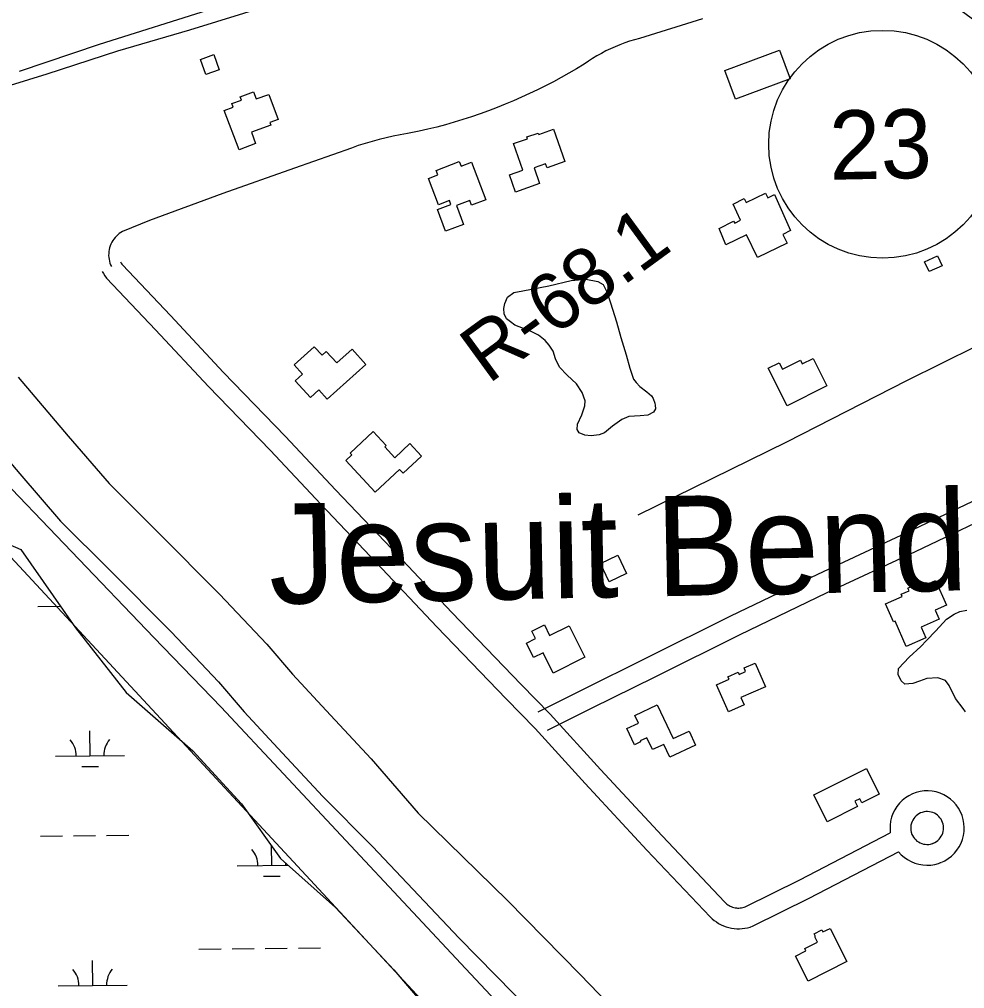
# Model space of a CAD drawing. Extents: x 3684037 to 3722149, y 433263 to 459021.
# Drawn here: x 3694344 to 3695714, y 454824 to 456228 of the extents above; entities that cross this region are included whole.
import ezdxf

# ---------------------------------------------------------------- set-up
doc = ezdxf.new("R2010")
doc.units = 0
for name, color, linetype in [('V-BLDG-OTLN', 7, 'Continuous'), ('V-LEVE-TOET', 7, 'Continuous'), ('V-RIVR-RANG-IDEN', 7, 'Continuous'), ('V-ROAD-CNTR', 7, 'Continuous'), ('V-ROAD-IDEN', 7, 'Continuous'), ('V-SITE-VEGE', 7, 'Continuous'), ('V-TOPO-GNAM-IDEN', 7, 'Continuous'), ('V-TOPO-SHOR', 7, 'Continuous'), ('V-WETL-SWMP', 7, 'Continuous')]:
    doc.layers.add(name, color=color, linetype=linetype)

msp = doc.modelspace()

# ---------------------------------------------------------------- linework, layer by layer
at = {"layer": 'V-BLDG-OTLN'}
for points in [[(3695366.6, 456153.9), (3695445.8, 456183.5), (3695461.3, 456141.9), (3695382.1, 456112.3)], [(3694626.2, 456176.8), (3694634, 456154.8), (3694614.7, 456147.9), (3694606.9, 456169.9)], [(3694705.9, 456119.2), (3694719.4, 456083.1), (3694707.3, 456078.5), (3694708.7, 456074.8), (3694680.7, 456064.3), (3694686.8, 456048.1), (3694662.8, 456039.1), (3694641.4, 456096), (3694654.2, 456100.8), (3694652.3, 456105.9), (3694666.3, 456111.1), (3694664.6, 456115.7), (3694683.8, 456122.9), (3694687.6, 456112.8)], [(3695118.6, 456068.9), (3695135.1, 456021.8), (3695109.1, 456012.7), (3695107.1, 456018.5), (3695090.5, 456012.7), (3695098.4, 455990), (3695063.4, 455977.7), (3695054.7, 456002.8), (3695073.8, 456009.5), (3695060.4, 456047.9), (3695080.9, 456055), (3695080, 456057.6), (3695096.3, 456063.3), (3695097, 456061.3)], [(3694988.1, 455930.9), (3694962.2, 455921.1), (3694950.3, 455952.3), (3694969.9, 455959.8), (3694967.8, 455965.4), (3694951.9, 455959.3), (3694937.4, 455997.5), (3694951, 456002.7), (3694948.6, 456009.1), (3694982, 456021.8), (3694984.5, 456015.1), (3694999.6, 456020.9), (3695020.3, 455966.4), (3694999.7, 455958.6), (3694997.1, 455965.5), (3694977.7, 455958.2)], [(3695457, 455903.6), (3695414.3, 455882.8), (3695398.3, 455915.6), (3695368.4, 455901.3), (3695358.4, 455925.1), (3695379.2, 455935.8), (3695381.1, 455932.7), (3695389.7, 455937), (3695378.8, 455960.4), (3695394.8, 455968.4), (3695397.6, 455962.6), (3695425.9, 455976.3), (3695429.3, 455969.4), (3695438.9, 455974), (3695462.2, 455921.9), (3695450.7, 455916.4)], [(3695681.6, 455871.1), (3695662.8, 455862.5), (3695656.3, 455876.9), (3695675.1, 455885.5)], [(3694846.4, 455728.1), (3694790.4, 455677.6), (3694778.2, 455691.1), (3694766.1, 455680.1), (3694744.1, 455704.5), (3694754.5, 455714), (3694742.5, 455727.4), (3694771.8, 455753.8), (3694783, 455741.3), (3694789.2, 455746.9), (3694804.3, 455730.2), (3694826.5, 455750.2)], [(3695514.8, 455697.2), (3695457.3, 455668), (3695429.7, 455722.5), (3695445.7, 455730.6), (3695450.6, 455721.1), (3695476.3, 455734.2), (3695479, 455728.8), (3695494.8, 455736.8)], [(3694823.8, 455599.6), (3694857.3, 455630.8), (3694876.2, 455610.6), (3694874, 455608.6), (3694888.6, 455593), (3694910.4, 455613.4), (3694927.2, 455595.3), (3694900.5, 455570.4), (3694895.1, 455576.1), (3694859.9, 455543.2), (3694817.4, 455588.8), (3694826.2, 455597)], [(3695199.3, 455413.3), (3695186.7, 455439.9), (3695211.9, 455451.8), (3695224.5, 455425.2)], [(3695629.8, 455319.3), (3695613.5, 455356.1), (3695611.4, 455355.2), (3695599.8, 455381.4), (3695623.7, 455392), (3695622.3, 455395.2), (3695633.9, 455400.3), (3695632.2, 455404.1), (3695644.4, 455409.6), (3695645.6, 455407), (3695657.6, 455412.3), (3695658.9, 455409.3), (3695672.1, 455415.1), (3695687.9, 455379.5), (3695671.5, 455372.2), (3695677.4, 455358.9), (3695651.4, 455347.4), (3695658.3, 455331.9)], [(3695141.1, 455349.7), (3695163.8, 455303.9), (3695117.9, 455281.1), (3695103.4, 455310.2), (3695089.7, 455303.4), (3695079.2, 455324.5), (3695092.5, 455331.1), (3695087.2, 455341.9), (3695105.3, 455351), (3695112.9, 455335.7)], [(3695410.6, 455295.6), (3695425.6, 455261.2), (3695390.2, 455245.7), (3695394.9, 455234.9), (3695372.1, 455224.9), (3695354.9, 455264.1), (3695372.9, 455272), (3695371.2, 455275.8), (3695386.1, 455282.4), (3695387.5, 455279.2), (3695396.9, 455283.3), (3695394.6, 455288.7)], [(3695287.2, 455159), (3695278.2, 455177.8), (3695261.9, 455170.1), (3695253.7, 455187.4), (3695244.1, 455182.9), (3695244.8, 455181.4), (3695236, 455177.2), (3695224.8, 455200.7), (3695241.5, 455208.7), (3695236.4, 455219.5), (3695268.9, 455235), (3695292.1, 455186.2), (3695314.9, 455197.1), (3695324.5, 455176.8)], [(3695495.7, 455104.5), (3695572, 455142.7), (3695590.5, 455105.6), (3695565.5, 455093.1), (3695562.6, 455098.9), (3695555.4, 455095.3), (3695559.2, 455087.6), (3695515.1, 455065.6)], [(3695519.4, 454911.3), (3695543.7, 454863.1), (3695487.8, 454834.8), (3695469.4, 454871.2), (3695484.4, 454878.8), (3695482.9, 454881.9), (3695501.1, 454891.1), (3695497.1, 454899), (3695498.4, 454899.7), (3695496.5, 454903.5), (3695507.5, 454909), (3695509, 454906)]]:
    msp.add_lwpolyline(points, close=True, dxfattribs=at)
at = {"layer": 'V-LEVE-TOET'}
for points in [[(3696627.9, 453001), (3696461.1, 453218.4), (3696075.3, 453606.9), (3695412.9, 454284.5), (3694747.3, 455001.3), (3694132.9, 455662.7), (3693840.2, 455975.5), (3693606.8, 456218.9), (3693390.2, 456442.3), (3693137.7, 456709), (3692943.4, 456915.7)], [(3693028.7, 456916.7), (3693038.7, 456906.9), (3693324.6, 456624.6), (3693426.3, 456503.8), (3693538.5, 456377.8), (3693732.6, 456194.4), (3693929.1, 455975.9), (3694180.6, 455706.2), (3694539.2, 455332.5), (3694636.7, 455231.9), (3694998.1, 454845.3), (3695305.2, 454518.5), (3695635.9, 454168.1), (3695971, 453817), (3696154, 453621.9), (3696470.1, 453290.7), (3696591.5, 453172.8), (3696683.7, 453049.7), (3696799.1, 452898.8)]]:
    msp.add_lwpolyline(points, dxfattribs=at)
at = {"layer": 'V-ROAD-CNTR'}
for points in [[(3695334.2, 456228.7), (3695242.9, 456200.2), (3695235.7, 456198.3), (3695228.7, 456196.1), (3695221.7, 456193.7), (3695214.7, 456191.1), (3695207.9, 456188.3), (3695201.2, 456185.3), (3695194.5, 456182.1), (3695188, 456178.7), (3695181.5, 456175), (3695175.2, 456171.2), (3695169, 456167.2), (3695162.9, 456162.9), (3695152, 456156.3), (3695140.9, 456149.8), (3695129.7, 456143.6), (3695118.4, 456137.5), (3695107, 456131.6), (3695095.5, 456125.9), (3695083.9, 456120.3), (3695072.2, 456115), (3695060.4, 456109.9), (3695048.6, 456104.9), (3695036.7, 456100.2), (3695024.4, 456095.5), (3695012, 456091), (3694999.6, 456086.7), (3694987.1, 456082.7), (3694974.5, 456078.9), (3694961.9, 456075.3), (3694949.2, 456072), (3694936.4, 456068.9), (3694923.6, 456066), (3694906.9, 456062.8), (3694896.5, 456060.9), (3694886.3, 456058.8), (3694876, 456056.5), (3694865.8, 456054), (3694855.7, 456051.2), (3694845.6, 456048.2), (3694835.6, 456045), (3694825.7, 456041.5), (3694743.3, 456012.5), (3694639.1, 455975.5), (3694533.2, 455936.7), (3694493.8, 455920.8), (3694491.4, 455919.3), (3694489.1, 455917.7), (3694486.9, 455915.9), (3694484.9, 455914), (3694483, 455911.9), (3694481.2, 455909.7), (3694479.6, 455907.4), (3694478.2, 455905), (3694477, 455902.4), (3694476, 455899.8), (3694475.1, 455897.1), (3694474.5, 455894.4), (3694474, 455891.6), (3694473.8, 455888.8), (3694473.7, 455886), (3694473.9, 455883.2), (3694474.3, 455880.4), (3694474.8, 455877.7), (3694475.6, 455875), (3694476.6, 455872.3), (3694477.7, 455869.8)], [(3696132.2, 455994.5), (3696130.6, 455989.7), (3696128.8, 455985), (3696126.9, 455980.4), (3696124.7, 455975.9), (3696122.3, 455971.5), (3696119.7, 455967.2), (3696116.9, 455963), (3696114, 455958.9), (3696110.8, 455955), (3696107.5, 455951.2), (3696104.1, 455947.6), (3696100.4, 455944.1), (3696096.7, 455940.8), (3696092.7, 455937.7), (3696010.6, 455892.6), (3695833, 455804.9), (3695630, 455704.1), (3695456, 455615.6), (3695240.7, 455510)], [(3694490.9, 455876.8), (3694492, 455874.8), (3694492.9, 455873.4), (3694493.7, 455872.3), (3694563.4, 455798.8), (3694640.3, 455716.6), (3694729.7, 455624.4), (3694803.1, 455546.1), (3694883.6, 455461.5), (3694971.3, 455368.7), (3695071.5, 455264.4), (3695113.5, 455221.4), (3695186.4, 455141.3), (3695275.8, 455045.1), (3695366.8, 454949.1), (3695368.3, 454947.7), (3695369.8, 454946.5), (3695371.3, 454945.3), (3695372.9, 454944.3), (3695374.5, 454943.5), (3695376.2, 454942.7), (3695378, 454942), (3695379.8, 454941.5), (3695381.7, 454941.1), (3695383.5, 454940.8), (3695385.4, 454940.7), (3695387.3, 454940.7), (3695389.2, 454940.8), (3695391, 454941), (3695392.9, 454941.4), (3695394.7, 454941.9), (3695396.1, 454942.4), (3695475.6, 454981.5), (3695606.6, 455049.7)], [(3694464.5, 455862.7), (3694466.1, 455859.7), (3694468.1, 455856.4), (3694470.7, 455853), (3694541.6, 455778.2), (3694618.5, 455695.9), (3694708, 455603.7), (3694781.3, 455525.5), (3694861.8, 455440.9), (3694949.5, 455348), (3695049.9, 455243.5), (3695091.7, 455200.8), (3695164.3, 455121), (3695253.9, 455024.6), (3695345.5, 454928), (3695348.3, 454925.3), (3695351.3, 454922.8), (3695354.5, 454920.5), (3695357.8, 454918.4), (3695361.3, 454916.5), (3695364.9, 454914.9), (3695368.6, 454913.5), (3695372.4, 454912.4), (3695376.3, 454911.6), (3695380.2, 454911), (3695384.1, 454910.7), (3695388.1, 454910.7), (3695392, 454910.9), (3695395.9, 454911.4), (3695399.8, 454912.2), (3695403.6, 454913.2), (3695407.7, 454914.7), (3695489.1, 454954.8), (3695618.6, 455022.2)], [(3696079.8, 455661.5), (3696015.7, 455632.4), (3695912.6, 455584.1), (3695784.2, 455524.1), (3695642.8, 455456.8), (3695513.7, 455396.8), (3695388.4, 455336.4), (3695265.4, 455275.3), (3695174.1, 455230.1), (3695109.3, 455197.7)], [(3695771.4, 455551.3), (3695630, 455484), (3695500.9, 455423.9), (3695375.2, 455363.3), (3695252, 455302.2), (3695160.7, 455257), (3695095.9, 455224.6)], [(3695681.1, 455007.1), (3695685.7, 455009.3), (3695690.7, 455012.4), (3695695.3, 455016), (3695699.5, 455020), (3695703.2, 455024.6), (3695706.5, 455029.4), (3695709.1, 455034.7), (3695711.2, 455040.1), (3695712.7, 455045.8), (3695713.6, 455051.6), (3695713.8, 455057.5), (3695713.4, 455063.3), (3695712.3, 455069.1), (3695710.7, 455074.7), (3695708.4, 455080.1), (3695705.6, 455085.3), (3695702.2, 455090), (3695698.3, 455094.4), (3695693.9, 455098.4), (3695689.2, 455101.8), (3695684.1, 455104.7), (3695678.7, 455107.1), (3695673.1, 455108.8), (3695667.4, 455109.9), (3695661.5, 455110.4), (3695655.7, 455110.3), (3695649.8, 455109.5), (3695644.2, 455108.1), (3695638.6, 455106), (3695633.4, 455103.4), (3695628.5, 455100.2), (3695623.9, 455096.6), (3695619.8, 455092.4), (3695616.1, 455087.8), (3695613, 455082.9), (3695610.4, 455077.6), (3695608.4, 455072.1), (3695607, 455066.4), (3695606.3, 455060.6), (3695606.2, 455054.7), (3695606.6, 455049.6)], [(3695668.3, 455034.2), (3695671.3, 455035.7), (3695673.5, 455037), (3695675.6, 455038.6), (3695677.4, 455040.4), (3695679.1, 455042.4), (3695680.5, 455044.6), (3695681.7, 455046.9), (3695682.6, 455049.3), (3695683.3, 455051.8), (3695683.7, 455054.4), (3695683.8, 455057), (3695683.6, 455059.6), (3695683.1, 455062.1), (3695682.4, 455064.6), (3695681.4, 455067), (3695680.1, 455069.3), (3695678.6, 455071.4), (3695676.9, 455073.3), (3695675, 455075.1), (3695672.9, 455076.6), (3695670.6, 455077.9), (3695668.3, 455078.9), (3695665.8, 455079.7), (3695663.2, 455080.2), (3695660.7, 455080.4), (3695658.1, 455080.3), (3695655.5, 455080), (3695653, 455079.3), (3695650.5, 455078.4), (3695648.2, 455077.3), (3695646.1, 455075.9), (3695644, 455074.3), (3695642.2, 455072.4), (3695640.6, 455070.4), (3695639.2, 455068.2), (3695638.1, 455065.9), (3695637.2, 455063.4), (3695636.6, 455060.9), (3695636.2, 455058.3), (3695636.2, 455055.8), (3695636.4, 455053.2), (3695636.9, 455050.7), (3695638, 455047.4), (3695638.7, 455045.9), (3695640.1, 455043.5), (3695641.6, 455041.5), (3695643.4, 455039.6), (3695645.3, 455037.8), (3695647.4, 455036.4), (3695649.7, 455035.1), (3695652.1, 455034.1), (3695654.6, 455033.4), (3695657.2, 455033), (3695659.7, 455032.8), (3695662.3, 455032.9), (3695664.9, 455033.3), (3695667.6, 455034), (3695668.9, 455034.5), (3695669.1, 455034.6)], [(3695618.6, 455022.2), (3695622.4, 455018), (3695626.8, 455014.2), (3695631.6, 455010.8), (3695636.8, 455008), (3695642.2, 455005.8), (3695647.8, 455004.1), (3695653.6, 455003.1), (3695659.5, 455002.8), (3695665.3, 455003), (3695671.1, 455003.9), (3695676.6, 455005.4), (3695679.6, 455006.5), (3695680.3, 455006.8)]]:
    msp.add_lwpolyline(points, dxfattribs=at)
for points in [[(3695024.3, 456943.2), (3695152.1, 456769.7), (3695409.8, 456485.5), (3695651.2, 456283.5), (3695889.4, 456120.4), (3696136.9, 455985.7), (3696236.4, 455936), (3696394, 455863.1), (3696621.9, 455754.9), (3696886.1, 455629.6), (3697071.3, 455542.4), (3697240.7, 455456.7), (3697428.9, 455333.1), (3697699.2, 455127.1), (3697849.7, 454985.5), (3697955.2, 454875.4)], [(3695071.9, 456943.7), (3695242.5, 456743.3), (3695448.6, 456526), (3695685.1, 456328.2), (3695918.7, 456168.2), (3696162.8, 456035.3), (3696260.6, 455986.4), (3696417.7, 455913.7), (3696645.9, 455805.4), (3696910, 455680.2), (3697095.9, 455592.7), (3697268.8, 455505.2), (3697461.2, 455378.7), (3697735.5, 455169.8), (3697889, 455025.2), (3697995.6, 454914.1)]]:
    msp.add_spline(points, degree=3, dxfattribs=at)
at = {"layer": 'V-ROAD-IDEN'}
msp.add_circle((3695595.4, 456047), 165, dxfattribs=at)
at = {"layer": 'V-SITE-VEGE'}
for points in [[(3694625.9, 456243.8), (3694460.1, 456191.7), (3694344, 456152.2)], [(3695715.6, 455224.8), (3695712, 455229.5), (3695701.1, 455244.2), (3695691.9, 455263), (3695686.5, 455270.1), (3695675.7, 455274.1), (3695659.7, 455273.2), (3695649.1, 455269.5), (3695639.1, 455265.8), (3695627.8, 455265.1), (3695622.4, 455269.7), (3695618.1, 455279.2), (3695618.6, 455287.5), (3695633.8, 455304.3), (3695650.8, 455319.4), (3695658.9, 455328.4), (3695672.4, 455342.2), (3695688.2, 455359.1), (3695699.3, 455366.4), (3695707.6, 455370), (3695717.6, 455372)]]:
    msp.add_lwpolyline(points, dxfattribs=at)
msp.add_lwpolyline([(3695244.3, 455653.5), (3695227.7, 455652.6), (3695217.7, 455648.3), (3695204.2, 455638.7), (3695192.4, 455629), (3695184.8, 455625.9), (3695172.9, 455624.6), (3695164, 455625.6), (3695155.7, 455629.1), (3695152.6, 455633.8), (3695153.1, 455641.5), (3695159.4, 455655.2), (3695164, 455668.3), (3695164.5, 455675.5), (3695160.2, 455687.3), (3695151.7, 455700.2), (3695138.4, 455712.5), (3695127, 455724.2), (3695121.5, 455736), (3695117.8, 455747.2), (3695112.3, 455756), (3695106.3, 455763), (3695096.7, 455770.6), (3695085.3, 455776.4), (3695062.6, 455784.9), (3695056, 455789.6), (3695050.6, 455794.3), (3695047, 455801.3), (3695046.3, 455809), (3695047.9, 455816.2), (3695052, 455825.7), (3695060.8, 455832.4), (3695073.8, 455834.9), (3695111.6, 455842), (3695144.2, 455849.6), (3695165.5, 455851.7), (3695182.8, 455848.4), (3695190.5, 455843.7), (3695195.4, 455834.3), (3695201, 455817.2), (3695209.7, 455790), (3695216, 455767), (3695224, 455742.2), (3695229.1, 455722.7), (3695234.6, 455706.7), (3695238.3, 455702), (3695243.7, 455696.2), (3695253.9, 455688.6), (3695260.5, 455682.8), (3695262.9, 455678.7), (3695265.4, 455672.2), (3695266, 455669.2), (3695266.1, 455663.9), (3695264.9, 455661.5), (3695263.2, 455659.1), (3695255, 455654.8)], close=True, dxfattribs=at)
at = {"layer": 'V-TOPO-SHOR'}
for points in [[(3695389.8, 456448.9), (3695332, 456429.6), (3695229.2, 456400.4), (3695146.4, 456376.8), (3695027.7, 456343.2), (3694923.2, 456311.6), (3694805.7, 456273.9), (3694708.2, 456248.3), (3694590.7, 456212.4), (3694486.8, 456182), (3694384, 456148.7), (3694271.3, 456114), (3694187.9, 456089.8), (3694079.2, 456057), (3694030.7, 456036.8)], [(3694342.4, 455709.5), (3694415.1, 455624.3), (3694474.3, 455555.6), (3694545.5, 455484.5), (3694634.4, 455395.5), (3694703, 455323), (3694740.3, 455279.4), (3694789.2, 455226.6), (3694854.4, 455156.7), (3694922.4, 455078.1), (3695051.9, 454951.6), (3695157.1, 454844.2), (3695252.1, 454745.9)], [(3694272.3, 455655), (3694345.1, 455569.8), (3694404.2, 455501.1), (3694475.4, 455430), (3694564.3, 455341), (3694632.9, 455268.5), (3694670.3, 455224.9), (3694719.2, 455172.1), (3694784.4, 455102.2), (3694856.3, 455029.7), (3694981.8, 454897.1), (3695087, 454789.7)]]:
    msp.add_lwpolyline(points, dxfattribs=at)
at = {"layer": 'V-WETL-SWMP'}
for p, q in [((3694370.9, 455377.6), (3694402.9, 455377.9)), ((3694446.9, 455161.2), (3694446.4, 455197.2)), ((3694396.9, 455160.6), (3694496.9, 455161.8)), ((3694435, 455145.6), (3694459, 455145.9)), ((3694374.8, 455044.9), (3694406.8, 455045.3)), ((3694422.8, 455045.5), (3694454.8, 455045.9)), ((3694470.8, 455046), (3694502.8, 455046.4)), ((3694710.2, 455002.4), (3694709.8, 455030.9)), ((3694660.2, 455001.8), (3694733.9, 455002.7)), ((3694698.3, 454986.8), (3694722.3, 454987.1)), ((3694604.7, 454881.1), (3694636.7, 454881.5)), ((3694652.7, 454881.6), (3694684.7, 454882)), ((3694700.7, 454882.2), (3694732.7, 454882.6)), ((3694748.7, 454882.8), (3694780.7, 454883.1)), ((3694450.7, 454828.5), (3694450.3, 454864.5)), ((3694400.7, 454828), (3694500.7, 454829.1))]:
    msp.add_line(p, q, dxfattribs=at)
msp.add_lwpolyline([(3694203.9, 455521.9), (3694346.4, 455459.8), (3694425.7, 455346.6), (3694499.3, 455253.1), (3694595.6, 455168.2), (3694666.4, 455091.7), (3694723, 455012.4), (3694802.3, 454941.6), (3694887.3, 454851), (3694955.2, 454771.7), (3695028.9, 454712.2)], dxfattribs=at)
for centre, start, end in [((3694502.1, 455162.3), 139.8949, 181.4385), ((3694391.6, 455161), 359.8949, 41.4385), ((3694654.9, 455002.2), 359.8949, 41.4385), ((3694765.4, 455003.5), 176.0108, 181.4385), ((3694395.5, 454828.4), 359.8949, 41.4385), ((3694506, 454829.7), 139.8949, 181.4385)]:
    msp.add_arc(centre, 35.2, start, end, dxfattribs=at)

# ---------------------------------------------------------------- texts
at = {"layer": 'V-RIVR-RANG-IDEN'}
msp.add_text('R-68.1', height=83, rotation=36.1203, dxfattribs=at).set_placement((3695024, 455698.7))
at = {"layer": 'V-ROAD-IDEN'}
msp.add_text('23', height=100, rotation=1.1352, dxfattribs=at).set_placement((3695518.9, 455995.5))
at = {"layer": 'V-TOPO-GNAM-IDEN'}
msp.add_text('Jesuit Bend', height=145, rotation=1.1351, dxfattribs=at).set_placement((3694707.1, 455381))

doc.saveas('drawing.dxf')
